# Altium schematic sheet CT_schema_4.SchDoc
size 300 x 247 mm
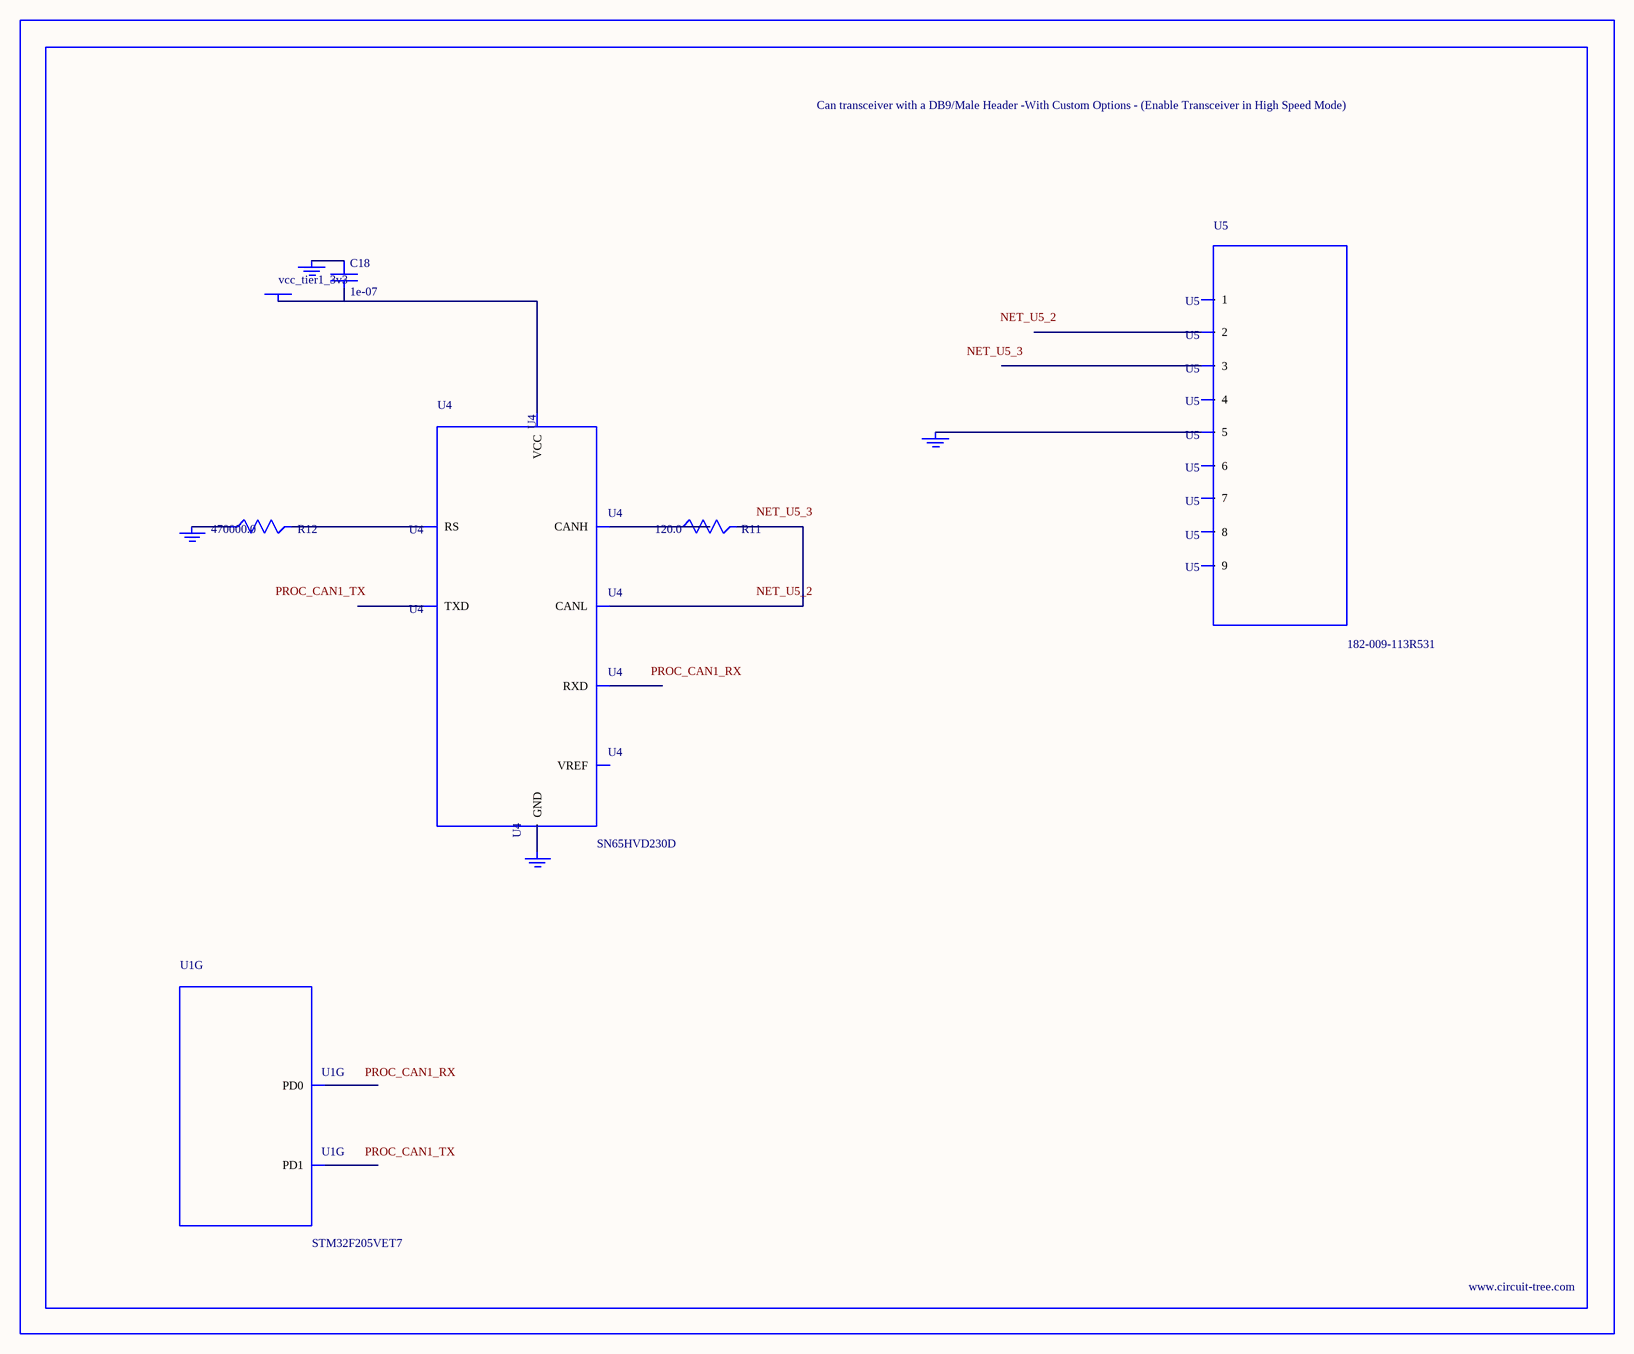
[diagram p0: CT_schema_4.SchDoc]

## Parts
BORDER3  (no value)
C18  1e-07  [C0402]
GND_INSTANCE_3_0  (no value)
GND_INSTANCE_3_1  (no value)
GND_INSTANCE_3_2  (no value)
GND_INSTANCE_3_3  (no value)
POWER_INSTANCE_3_0  vcc_tier1_3v3
R11  120.0  [R0603]
R12  470000.0  [R0603]
U1  STM32F205VET7  [LQFP100]  (part G of 11)
U4  SN65HVD230D  [SOIC-8]
U5  182-009-113R531  [182-009-MALE]

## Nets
NetC18_1: C18.1 GND_INSTANCE_3_0.0(GND)
NetC18_2: C18.2 POWER_INSTANCE_3_0.0(PWR) U4.3(VCC)
NetGND_INSTANCE_3_1_0: GND_INSTANCE_3_1.0(GND) R12.1
NetGND_INSTANCE_3_2_0: GND_INSTANCE_3_2.0(GND) U4.2(GND)
NetGND_INSTANCE_3_3_0: GND_INSTANCE_3_3.0(GND) U5.5
NetR11_1: R11.1 U4.7(CANH)
NetR11_2: R11.2 U4.6(CANL)
NetR12_2: R12.2 U4.8(RS)

Not connected (* = marked no-connect by the designer): U1 81(PD0) 82(PD1); U4 1(TXD) 4(RXD) 5(VREF); U5 1 2 3 4 6 7 8 9

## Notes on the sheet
- Labels drawn without touching a wire or pin: NET_U5_2, NET_U5_3, PROC_CAN1_RX, PROC_CAN1_TX

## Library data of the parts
BORDER3 = BORDER_PAGE3
C18 = C0402C104K3RACTU
GND_INSTANCE_3_0-GND_INSTANCE_3_3 = GND
POWER_INSTANCE_3_0 = PWR
R11 = RC0603JR-07120RL
R12 = RC0603JR-07470KL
